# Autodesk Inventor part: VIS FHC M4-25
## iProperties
Created: 2004-11
Part Number: VIS FHC M4-25
Document SubType Name: Modeling
Designer: Bruno
Manufacturer: Standard
Standards Organization: Custom
Author: Bruno
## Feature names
1. Base1
